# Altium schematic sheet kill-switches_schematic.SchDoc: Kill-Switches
size A4; Organization: UFSC; DocumentNumber: 7; SheetNumber: 7; SheetTotal: 8
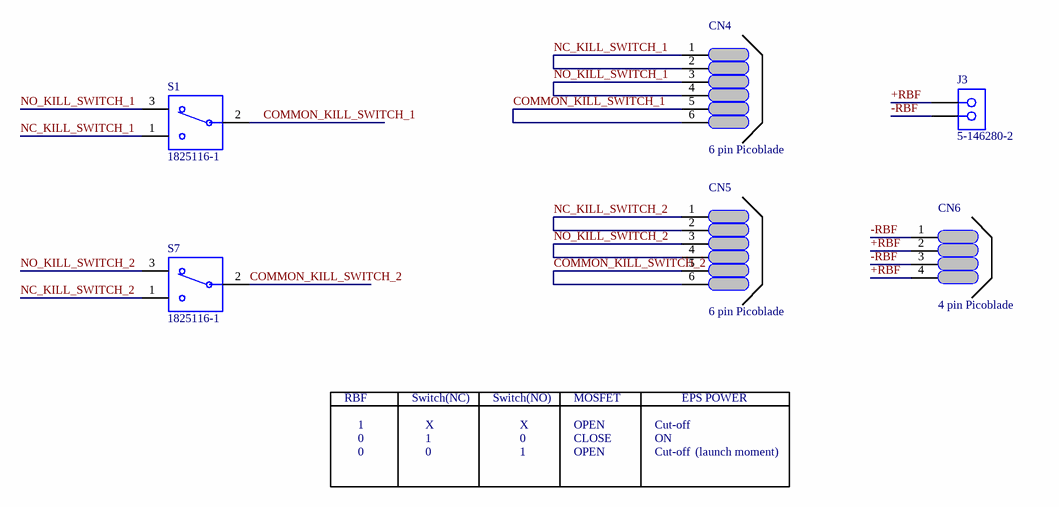
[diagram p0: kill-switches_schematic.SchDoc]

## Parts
CN4  6 pin Picoblade  [PICO BLADE 0533980671]
CN5  6 pin Picoblade  [PICO BLADE 0533980671]
CN6  4 pin Picoblade  [PICO BLADE 0533980471]
J3  5-146280-2  [PIN BAR 2 2.54mm 180 GRAUS]
S1  1825116-1  [SW_1825116-1]
S7  1825116-1  [SW_1825116-1]

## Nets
+RBF: CN6.2 CN6.4 J3.1
-RBF: CN6.1 CN6.3 J3.2
COMMON_KILL_SWITCH_1: CN4.5 CN4.6 S1.2
COMMON_KILL_SWITCH_2: CN5.5 CN5.6 S7.2
NC_KILL_SWITCH_1: CN4.1 CN4.2 S1.1
NC_KILL_SWITCH_2: CN5.1 CN5.2 S7.1
NO_KILL_SWITCH_1: CN4.3 CN4.4 S1.3
NO_KILL_SWITCH_2: CN5.3 CN5.4 S7.3

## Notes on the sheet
- RBF
- Switch(NC)
- Switch(NO)
- MOSFET
- EPS POWER
- 1
- 0
- X
- OPEN
- CLOSE
- Cut-off
- ON
- (launch moment)

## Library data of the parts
CN4 CN5 = 53398-0671: 1.25mm Pitch PicoBlade™ Header, Surface Mount, Vertical, 6 Circuits; Manufacturer: Molex; Body Plating: Tin; Contact Resistance: 20mR; Voltage Rating: 125V; Current Rating: 1A; Number of Positions: 6; Insulation Resistance: 100MR; Gender: Male; Glow Wire Compliant: Non-compliant
CN6 = 0533980471: 1.25mm Pitch PicoBlade™ Header, Surface Mount, Vertical, 4 Circuits; Manufacturer: Molex; Manufacturer Part Number: 53398-0471; N of Positions: 4; Body Plating: Tin; Gender: Male; Current Rating: 1A; Voltage Rating: 125V; Contact Resistance: 20mR; Insulation Resistance: 100MR; Glow Wire Compliant: Non-compliant
J3 = 5-146280-2: 02 MODII HDR SRST B/A .100CL; MF: TE Connectivity; Product_Type: Connector; Number_of_Positions: 2; Centerline_Pitch: 2.54 mm[.1 in]
S1 S7 = 1825116-1: Slide Switch SPDT Through Hole, Right Angle; MF: TE Connectivity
